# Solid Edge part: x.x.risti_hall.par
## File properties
Author: Romil
Template: iso part.par
Last saved by: Romil
Revision: 39
Application: Solid Edge
Accuracy: 0.990
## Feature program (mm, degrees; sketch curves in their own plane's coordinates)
sketch for "unnamed Protrusion 1" plane through (0, 0, 0) normal (1, 0, 0) x-axis (0, 1, 0)
extrude "unnamed Protrusion 1" add finite 7.8 symmetric
sketch for "unnamed RevolvedCutout 1" plane through (0, 0, 0) normal (0, -1, 0) x-axis (1, 0, 0)
revolve "unnamed RevolvedCutout 1" cut finite 360 deg
sketch for "ExtrudedProtrusion_11" plane through (0, 0, 11.6) normal (0, 0, 1) x-axis (1, 0, 0)
extrude "ExtrudedProtrusion_11" add finite 6.8 along -normal
sketch for "unnamed Protrusion 2" plane through (0, 0, 11.6) normal (0, 0, 1) x-axis (1, 0, 0)
extrude "unnamed Protrusion 2" add finite 1.2 along -normal
sketch for "unnamed Protrusion 3" plane through (0, 0, 0) normal (0, 0, 1) x-axis (1, 0, 0)
extrude "unnamed Protrusion 3" add to key point along +normal
sketch for "unnamed Protrusion 4" plane through (0, 0, 0) normal (0, 0, 1) x-axis (1, 0, 0)
extrude "unnamed Protrusion 4" add to key point along +normal
mirror "unnamed Mirror 1" of "unnamed Protrusion 3" about plane through (0, 0, 0) normal (1, 0, 0)
extrude "unnamed Protrusion 5" add finite 4.8
sketch used by "unnamed Protrusion 6" plane through (0, 0, 0) normal (0, -1, 0) x-axis (1, 0, 0)
extrude "unnamed Protrusion 6" add to key point symmetric
sketch for "unnamed Cutout 1" plane through (0, 0, 11.6) normal (0, 0, 1) x-axis (1, 0, 0)
extrude "unnamed Cutout 1" cut to key point symmetric
sketch for "unnamed Cutout 2" plane through (0, 0, 0) normal (1, 0, 0) x-axis (0, 1, 0)
extrude "unnamed Cutout 2" cut finite 47.4999 symmetric
sketch for "ExtrudedCutout_25" plane through (0, 0, 0) normal (0, -1, 0) x-axis (1, 0, 0)
  circle centre (0, 0) radius 3.6
extrude "ExtrudedCutout_25" cut finite 152.9831 symmetric
sketch used by "ExtrudedCutout_26" plane through (0, 0, 0) normal (0, -1, 0) x-axis (1, 0, 0)
  line (0.6, 9.8798) -> (0.6, 5.3861)
  line (-0.6, 5.3861) -> (-0.6, 9.8798)
  line (0.6, 5.3861) -> (0.6, 4.8)
  line (0.6, 4.8) -> (-0.6, 4.8)
  line (-0.6, 4.8) -> (-0.6, 5.3861)
  line (-0.6, 9.8798) -> (-0.6, 10.4)
  line (-0.6, 10.4) -> (0.6, 10.4)
  line (0.6, 10.4) -> (0.6, 9.8798)
extrude "ExtrudedCutout_26" cut finite 35.3769 symmetric
fillet "unnamed Round 1"
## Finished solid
Body 1: solid body, 120 faces, 320 edges, 200 vertices.
  Faces by surface: cylinder 63, plane 43, blend 12, torus 2
  Edges by curve: line 170, circle 94, intersection 32, ellipse 24
Bounding box of the edges (mm; curved faces can reach further): 7.800 x 7.200 x 15.200, from (-3.9, -3.6, -3.6) to (3.9, 3.6, 11.6).
Cylindrical faces by radius (mm): R0.1 x8, R0.2 x8, R0.4 x24, R2.2319 x4, R2.35 x8, R2.7009 x2, R3.0587 x3, R3.6 x6
Toroidal faces (ring radius, tube radius in mm): R3.3 r0.3 x2
Planar faces by outward normal: +x 9, +y 6, +z 6, -x 9, -y 6, -z 7
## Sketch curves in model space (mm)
arc centre (0.975, -0.975, 11.6) radius 0.1 from (0.875, -0.975, 11.6) through (0.9064, -0.9023, 11.6) to (0.975, -0.875, 11.6)
line (0.975, -0.875, 11.6) -> (2.181, -0.875, 11.6)
arc centre (0, 0, 11.6) radius 2.35 from (2.181, 0.875, 11.6) through (2.35, 0, 11.6) to (2.181, -0.875, 11.6)
line (2.181, 0.875, 11.6) -> (0.975, 0.875, 11.6)
arc centre (0.975, 0.975, 11.6) radius 0.1 from (0.975, 0.875, 11.6) through (0.9023, 0.9064, 11.6) to (0.875, 0.975, 11.6)
line (0.875, 0.975, 11.6) -> (0.875, 2.181, 11.6)
arc centre (0, 0, 11.6) radius 2.35 from (-0.875, 2.181, 11.6) through (0, 2.35, 11.6) to (0.875, 2.181, 11.6)
line (-0.875, 2.181, 11.6) -> (-0.875, 0.975, 11.6)
arc centre (-0.975, 0.975, 11.6) radius 0.1 from (-0.875, 0.975, 11.6) through (-0.9064, 0.9023, 11.6) to (-0.975, 0.875, 11.6)
line (-0.975, 0.875, 11.6) -> (-2.181, 0.875, 11.6)
arc centre (0, 0, 11.6) radius 2.35 from (-2.181, -0.875, 11.6) through (-2.35, 0, 11.6) to (-2.181, 0.875, 11.6)
line (-2.181, -0.875, 11.6) -> (-0.975, -0.875, 11.6)
arc centre (-0.975, -0.975, 11.6) radius 0.1 from (-0.975, -0.875, 11.6) through (-0.9023, -0.9064, 11.6) to (-0.875, -0.975, 11.6)
line (-0.875, -0.975, 11.6) -> (-0.875, -2.181, 11.6)
arc centre (0, 0, 11.6) radius 2.35 from (0.875, -2.181, 11.6) through (0, -2.35, 11.6) to (-0.875, -2.181, 11.6)
line (0.875, -2.181, 11.6) -> (0.875, -0.975, 11.6)
circle centre (0, 0, 11.6) radius 2.7009
arc centre (-0.975, -0.975, 0) radius 0.1 from (-0.975, -0.875, 0) through (-0.9023, -0.9064, 0) to (-0.875, -0.975, 0)
line (-0.875, -0.975, 0) -> (-0.875, -2.181, 0)
arc centre (0, 0, 0) radius 2.35 from (0.875, -2.181, 0) through (0, -2.35, 0) to (-0.875, -2.181, 0)
line (0.875, -2.181, 0) -> (0.875, -0.975, 0)
arc centre (0.975, -0.975, 0) radius 0.1 from (0.875, -0.975, 0) through (0.9064, -0.9023, 0) to (0.975, -0.875, 0)
line (0.975, -0.875, 0) -> (2.181, -0.875, 0)
arc centre (0, 0, 0) radius 2.35 from (2.181, 0.875, 0) through (2.35, 0, 0) to (2.181, -0.875, 0)
line (2.181, 0.875, 0) -> (0.975, 0.875, 0)
arc centre (0.975, 0.975, 0) radius 0.1 from (0.975, 0.875, 0) through (0.9023, 0.9064, 0) to (0.875, 0.975, 0)
line (0.875, 0.975, 0) -> (0.875, 2.181, 0)
arc centre (0, 0, 0) radius 2.35 from (-0.875, 2.181, 0) through (0, 2.35, 0) to (0.875, 2.181, 0)
line (-0.875, 2.181, 0) -> (-0.875, 0.975, 0)
arc centre (-0.975, 0.975, 0) radius 0.1 from (-0.875, 0.975, 0) through (-0.9064, 0.9023, 0) to (-0.975, 0.875, 0)
line (-0.975, 0.875, 0) -> (-2.181, 0.875, 0)
arc centre (0, 0, 0) radius 2.35 from (-2.181, -0.875, 0) through (-2.35, 0, 0) to (-2.181, 0.875, 0)
line (-2.181, -0.875, 0) -> (-0.975, -0.875, 0)
arc centre (1.1947, 3.1832, 0) radius 0.2 from (1.3919, 3.2163, 0) through (1.349, 3.3104, 0) to (1.2649, 3.3705, 0)
arc centre (3.593, 3.586, 0) radius 2.2319 from (3.219, 1.3856, 0) through (1.9675, 2.0565, 0) to (1.3919, 3.2163, 0)
arc centre (3.1855, 1.1884, 0) radius 0.2 from (3.3729, 1.2583, 0) through (3.313, 1.3425, 0) to (3.219, 1.3856, 0)
arc centre (0, 0, 0) radius 3.6 from (3.3729, 1.2583, 0) through (3.6, 0, 0) to (3.3729, -1.2583, 0)
arc centre (3.1855, -1.1884, 0) radius 0.2 from (3.219, -1.3856, 0) through (3.313, -1.3425, 0) to (3.3729, -1.2583, 0)
arc centre (3.593, -3.586, 0) radius 2.2319 from (3.219, -1.3856, 0) through (1.9675, -2.0565, 0) to (1.3919, -3.2163, 0)
arc centre (1.1947, -3.1832, 0) radius 0.2 from (1.2649, -3.3705, 0) through (1.349, -3.3104, 0) to (1.3919, -3.2163, 0)
arc centre (0, 0, 0) radius 3.6 from (1.2649, -3.3705, 0) through (0, -3.6, 0) to (-1.2649, -3.3705, 0)
arc centre (-1.1947, -3.1832, 0) radius 0.2 from (-1.3919, -3.2163, 0) through (-1.349, -3.3104, 0) to (-1.2649, -3.3705, 0)
arc centre (-3.593, -3.586, 0) radius 2.2319 from (-3.219, -1.3856, 0) through (-1.9675, -2.0565, 0) to (-1.3919, -3.2163, 0)
arc centre (-3.1855, -1.1884, 0) radius 0.2 from (-3.3729, -1.2583, 0) through (-3.313, -1.3425, 0) to (-3.219, -1.3856, 0)
arc centre (0, 0, 0) radius 3.6 from (-3.3729, -1.2583, 0) through (-3.6, 0, 0) to (-3.3729, 1.2583, 0)
arc centre (-3.1855, 1.1884, 0) radius 0.2 from (-3.219, 1.3856, 0) through (-3.313, 1.3425, 0) to (-3.3729, 1.2583, 0)
arc centre (-3.593, 3.586, 0) radius 2.2319 from (-3.219, 1.3856, 0) through (-1.9675, 2.0565, 0) to (-1.3919, 3.2163, 0)
arc centre (-1.1947, 3.1832, 0) radius 0.2 from (-1.2649, 3.3705, 0) through (-1.349, 3.3104, 0) to (-1.3919, 3.2163, 0)
arc centre (0, 0, 0) radius 3.6 from (-1.2649, 3.3705, 0) through (0, 3.6, 0) to (1.2649, 3.3705, 0)
line (3.6217, 0, 4.8) -> (3.6217, 0, 3.8)
line (3.6217, 0, 3.8) -> (-3.6217, 0, 3.8)
line (-3.6217, 0, 3.8) -> (-3.6217, 0, 4.8)
line (-3.6217, 0, 4.8) -> (3.6217, 0, 4.8)
line (2.7, 0, -0.6) -> (2.7, 0, 0.6)
line (2.7, 0, 0.6) -> (-2.7, 0, 0.6)
line (-2.7, 0, 0.6) -> (-2.7, 0, -0.6)
line (-2.7, 0, -0.6) -> (2.7, 0, -0.6)
line (-3.35, -0.6, 0) -> (-3.35, 0.6, 0)
line (-3.35, 0.6, 0) -> (3.35, 0.6, 0)
line (3.35, 0.6, 0) -> (3.35, -0.6, 0)
line (3.35, -0.6, 0) -> (-3.35, -0.6, 0)
line (0.6, 0, 5.3861) -> (0.6, 0, 4.8)
line (0.6, 0, 4.8) -> (-0.6, 0, 4.8)
line (-0.6, 0, 4.8) -> (-0.6, 0, 5.3861)
line (-0.6, 0, 5.3861) -> (-0.6, 0, 9.8798)
line (-0.6, 0, 9.8798) -> (-0.6, 0, 10.4)
line (-0.6, 0, 10.4) -> (0.6, 0, 10.4)
line (0.6, 0, 10.4) -> (0.6, 0, 9.8798)
line (0.6, 0, 9.8798) -> (0.6, 0, 5.3861)
line (-4.4651, 0, 0) -> (5.0671, 0, 0)
line (2.7, 0, 3.0587) -> (2.7, 0, 3.3)
arc centre (3, 0, 3.3) radius 0.3 from (2.7, 0, 3.3) through (2.7941, 0, 3.5182) to (3, 0, 3.6)
line (3, 0, 3.6) -> (3.9, 0, 3.6)
line (3.9, 0, 3.6) -> (3.9, 0, 4.041)
line (3.9, 0, 4.041) -> (-3.9, 0, 4.041)
line (-3.9, 0, 4.041) -> (-3.9, 0, 3.6)
line (-3.9, 0, 3.6) -> (-3, 0, 3.6)
arc centre (-3, 0, 3.3) radius 0.3 from (-2.7, 0, 3.3) through (-2.7941, 0, 3.5182) to (-3, 0, 3.6)
line (-2.7, 0, 3.3) -> (-2.7, 0, 3.0587)
line (-2.7, 0, 3.0587) -> (2.7, 0, 3.0587)
circle centre (0, 0, 7.9783) radius 2.4
circle centre (0, 0, 7.9783) radius 3.6217
line (-3.6217, -2.75, 0) -> (-3.6217, 1.953, 0)
line (-3.6217, -2.75, 0) -> (-2.7879, -2.75, 0)
line (-2.7879, 2.75, 0) -> (-2.7879, -2.75, 0)
line (-3.6217, 2.75, 0) -> (-2.7879, 2.75, 0)
line (-3.6217, 2.75, 0) -> (-3.6217, 1.953, 0)
circle centre (0, 0, 0) radius 3.6
arc centre (3.593, -3.586, 11.6) radius 2.2319 from (3.219, -1.3856, 11.6) through (1.9675, -2.0565, 11.6) to (1.3919, -3.2163, 11.6)
arc centre (3.1855, -1.1884, 11.6) radius 0.2 from (3.219, -1.3856, 11.6) through (3.313, -1.3425, 11.6) to (3.3729, -1.2583, 11.6)
arc centre (0, 0, 11.6) radius 3.6 from (3.3729, 1.2583, 11.6) through (3.6, 0, 11.6) to (3.3729, -1.2583, 11.6)
arc centre (3.1855, 1.1884, 11.6) radius 0.2 from (3.3729, 1.2583, 11.6) through (3.313, 1.3425, 11.6) to (3.219, 1.3856, 11.6)
arc centre (3.593, 3.586, 11.6) radius 2.2319 from (3.219, 1.3856, 11.6) through (1.9675, 2.0565, 11.6) to (1.3919, 3.2163, 11.6)
arc centre (1.1947, 3.1832, 11.6) radius 0.2 from (1.3919, 3.2163, 11.6) through (1.349, 3.3104, 11.6) to (1.2649, 3.3705, 11.6)
arc centre (0, 0, 11.6) radius 3.6 from (-1.2649, 3.3705, 11.6) through (0, 3.6, 11.6) to (1.2649, 3.3705, 11.6)
arc centre (-1.1947, 3.1832, 11.6) radius 0.2 from (-1.2649, 3.3705, 11.6) through (-1.349, 3.3104, 11.6) to (-1.3919, 3.2163, 11.6)
arc centre (-3.593, 3.586, 11.6) radius 2.2319 from (-3.219, 1.3856, 11.6) through (-1.9675, 2.0565, 11.6) to (-1.3919, 3.2163, 11.6)
arc centre (-3.1855, 1.1884, 11.6) radius 0.2 from (-3.219, 1.3856, 11.6) through (-3.313, 1.3425, 11.6) to (-3.3729, 1.2583, 11.6)
arc centre (0, 0, 11.6) radius 3.6 from (-3.3729, -1.2583, 11.6) through (-3.6, 0, 11.6) to (-3.3729, 1.2583, 11.6)
arc centre (-3.1855, -1.1884, 11.6) radius 0.2 from (-3.3729, -1.2583, 11.6) through (-3.313, -1.3425, 11.6) to (-3.219, -1.3856, 11.6)
arc centre (-3.593, -3.586, 11.6) radius 2.2319 from (-3.219, -1.3856, 11.6) through (-1.9675, -2.0565, 11.6) to (-1.3919, -3.2163, 11.6)
arc centre (-1.1947, -3.1832, 11.6) radius 0.2 from (-1.3919, -3.2163, 11.6) through (-1.349, -3.3104, 11.6) to (-1.2649, -3.3705, 11.6)
arc centre (0, 0, 11.6) radius 3.6 from (1.2649, -3.3705, 11.6) through (0, -3.6, 11.6) to (-1.2649, -3.3705, 11.6)
arc centre (1.1947, -3.1832, 11.6) radius 0.2 from (1.2649, -3.3705, 11.6) through (1.349, -3.3104, 11.6) to (1.3919, -3.2163, 11.6)
circle centre (0, 0, 8) radius 3.6
arc centre (0, -0.975, -0.975) radius 0.1 from (0, -0.975, -0.875) through (0, -0.9023, -0.9064) to (0, -0.875, -0.975)
line (0, -0.875, -0.975) -> (0, -0.875, -2.181)
arc centre (0, 0, 0) radius 2.35 from (0, 0.875, -2.181) through (0, 0, -2.35) to (0, -0.875, -2.181)
line (0, 0.875, -2.181) -> (0, 0.875, -0.975)
arc centre (0, 0.975, -0.975) radius 0.1 from (0, 0.875, -0.975) through (0, 0.9064, -0.9023) to (0, 0.975, -0.875)
line (0, 0.975, -0.875) -> (0, 2.181, -0.875)
arc centre (0, 0, 0) radius 2.35 from (0, 2.181, 0.875) through (0, 2.35, 0) to (0, 2.181, -0.875)
line (0, 2.181, 0.875) -> (0, 0.975, 0.875)
arc centre (0, 0.975, 0.975) radius 0.1 from (0, 0.975, 0.875) through (0, 0.9023, 0.9064) to (0, 0.875, 0.975)
line (0, 0.875, 0.975) -> (0, 0.875, 2.181)
arc centre (0, 0, 0) radius 2.35 from (0, -0.875, 2.181) through (0, 0, 2.35) to (0, 0.875, 2.181)
line (0, -0.875, 2.181) -> (0, -0.875, 0.975)
arc centre (0, -0.975, 0.975) radius 0.1 from (0, -0.875, 0.975) through (0, -0.9064, 0.9023) to (0, -0.975, 0.875)
line (0, -0.975, 0.875) -> (0, -2.181, 0.875)
arc centre (0, 0, 0) radius 2.35 from (0, -2.181, -0.875) through (0, -2.35, 0) to (0, -2.181, 0.875)
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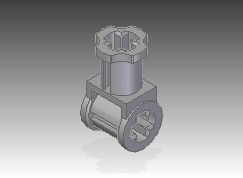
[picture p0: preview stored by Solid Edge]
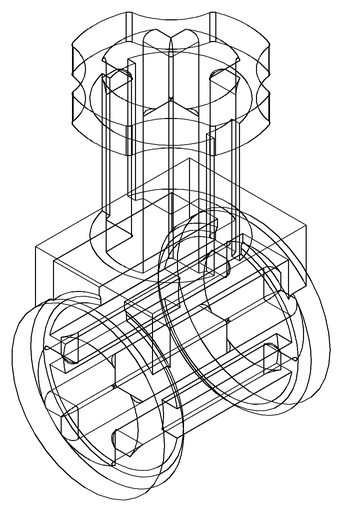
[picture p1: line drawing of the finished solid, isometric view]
